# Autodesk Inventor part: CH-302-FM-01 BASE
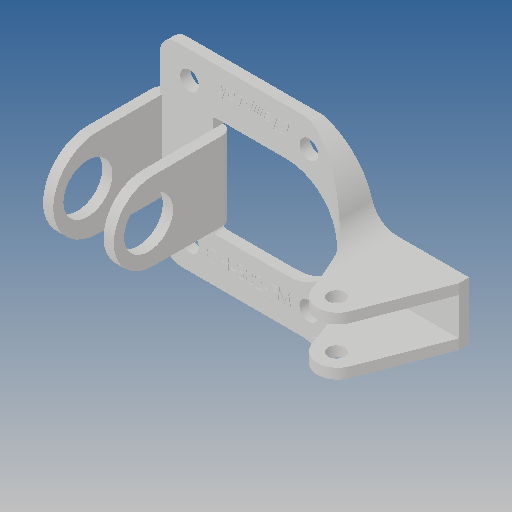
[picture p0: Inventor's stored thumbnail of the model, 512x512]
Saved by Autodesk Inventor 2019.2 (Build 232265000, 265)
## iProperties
Created: 2013-03
Part Number: CH-302-FM-01 BASE
Material: Ogólny
Document SubType Name: Modeling
Designer: CADENGINEERING4
Density: 1 g/cm^3
Appearance: Domyślna
Author: CADENGINEERING4
Revision Number: ÈÎºÎ
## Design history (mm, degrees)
feature "ÇÐ³ý-À­Éì23"
node "Bryła1"
